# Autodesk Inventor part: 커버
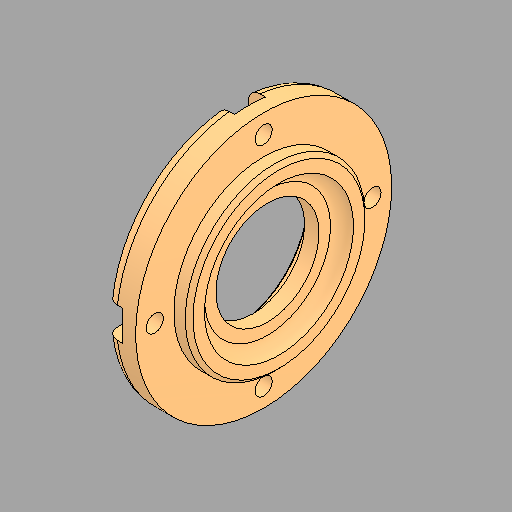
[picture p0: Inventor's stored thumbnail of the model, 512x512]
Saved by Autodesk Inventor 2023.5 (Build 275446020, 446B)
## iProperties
Created: 2025-07
Part Number: 커버
Material: 알루미늄 6061
Document SubType Name: Modeling
Designer: 1강의실14
Density: 2.7 g/cm^3
Appearance: 기본값
Author: jhkim
Sending System: Autodesk Inventor 2026
Preprocessor: ST-DEVELOPER v20.1
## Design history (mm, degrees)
feature "솔리드1"
node "솔리드2"
